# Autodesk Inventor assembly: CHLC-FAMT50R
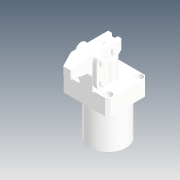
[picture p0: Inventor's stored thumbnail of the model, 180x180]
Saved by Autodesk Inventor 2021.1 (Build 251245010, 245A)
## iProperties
Created: 2019-04
Part Number: CHLC-FAMT50R
Description: STEP AP214
Document SubType Name: Assembly
Designer: user
Title: CHLC-FAMT50R.STEP
Revision Number: ÈÎºÎ
Sending System: SolidWorks 2016
Preprocessor: SwSTEP 2.0
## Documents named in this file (11)
- D:\Vault_2016\Projekty\Clamptek\Hydraulic\CHLC\CHLC-50\Inventor\CHLC-FAMT50R\CHLC-FAMT50R.iam
- D:\Vault_2016\Projekty\Clamptek\Hydraulic\CHLC\CHLC-50\Inventor\CHLC-FAMT50R\CHLC-FAMT50-benti.ipt
- D:\Vault_2016\Projekty\Clamptek\Hydraulic\CHLC\CHLC-50\Inventor\CHLC-FAMT50R\CHLC-50-01.ipt
- D:\Vault_2016\Projekty\Clamptek\Hydraulic\CHLC\CHLC-50\Inventor\CHLC-FAMT50R\CHLC-50-02.ipt
- D:\Vault_2016\Projekty\Clamptek\Hydraulic\CHLC\CHLC-50\Inventor\CHLC-FAMT50R\CHLC-50-03.ipt
- D:\Vault_2016\Projekty\Clamptek\Hydraulic\CHLC\CHLC-50\Inventor\CHLC-FAMT50R\CHLC-50-04.ipt
- D:\Vault_2016\Projekty\Clamptek\Hydraulic\CHLC\CHLC-50\Inventor\CHLC-FAMT50R\CHLC-50-06.ipt
- D:\Vault_2016\Projekty\Clamptek\Hydraulic\CHLC\CHLC-50\Inventor\CHLC-FAMT50R\CHLC-50-09.ipt
- D:\Vault_2016\Projekty\Clamptek\Hydraulic\CHLC\CHLC-50\Inventor\CHLC-FAMT50R\CZL20µ÷ËÙ·§.iam
- D:\Vault_2016\Projekty\Clamptek\Hydraulic\CHLC\CHLC-50\Inventor\CHLC-FAMT50R\M6LS.ipt
- D:\Vault_2016\Projekty\Clamptek\Hydraulic\CHLC\CHLC-50\Inventor\CHLC-FAMT50R\ZHIC.ipt
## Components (19 placed, 19 different names)
1. CHLC-FAMT50-benti_1
2. CHLC-50-01_2
3. CHLC-50-02_3
4. CHLC-50-03_4
5. CHLC-50-03_5
6. CHLC-50-04_6
7. CHLC-50-06_7
8. CHLC-50-09_8
9. CZL20µ÷ËÙ·§_9 [sub-assembly]
10. M6LS_10
11. ZHIC_11
12. CHLC-50-06_12
13. CHLC-50-06_13
14. CHLC-50-06_14
15. CHLC-50-06_15
16. CHLC-50-06_16
17. CHLC-50-04_17
18. M6LS_18
19. M6LS_19
